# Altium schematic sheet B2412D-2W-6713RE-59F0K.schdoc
size 277 x 190 mm; Device: default297x210; Symbol: default297x210; Name: default297x210; Date: 2026.04.17; Rev: V1.0; Size: "A4"; Id: /; File: B2412D-2W-6713RE-59F0K; Sheet: /
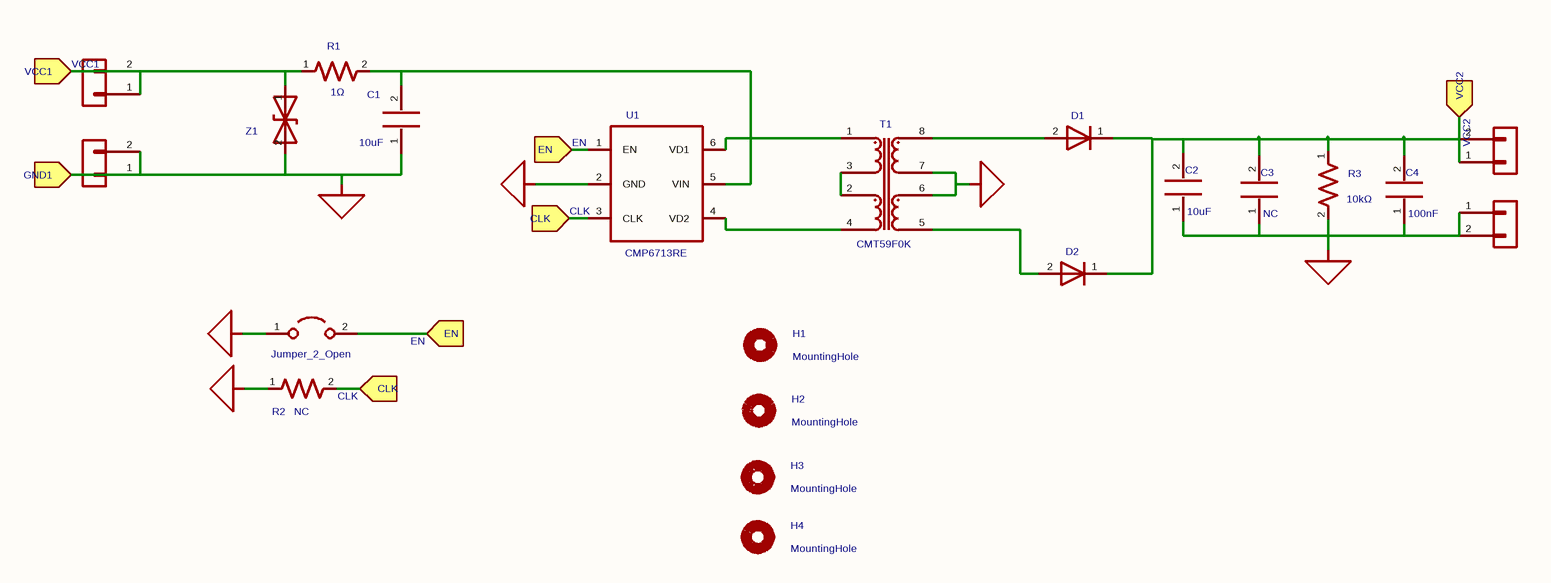
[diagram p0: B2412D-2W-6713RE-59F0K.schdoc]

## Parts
C1  10uF  [MYLibrary:C0805]
C2  10uF  [MYLibrary:C0805]
C3  value NC  [MYLibrary:C0805]  (hidden comment: My_Library_C)
C4  100nF  [MYLibrary:C0603]
D1  B5819WS  [MYLibrary:SOD-123-323]  (value not drawn)
D2  B5819WS  [MYLibrary:SOD-123-323]  (value not drawn)
H1  value MountingHole  [MountingHole:MountingHole_3.2mm_M3]  (hidden comment: Mechanical_MountingHole)
H2  value MountingHole  [MountingHole:MountingHole_3.2mm_M3]  (hidden comment: Mechanical_MountingHole)
H3  value MountingHole  [MountingHole:MountingHole_3.2mm_M3]  (hidden comment: Mechanical_MountingHole)
H4  value MountingHole  [MountingHole:MountingHole_3.2mm_M3]  (hidden comment: Mechanical_MountingHole)
J1  HX PZ2.54-1x2P ZZ  [Connector_PinHeader_2.54mm:PinHeader_1x02_P2.54mm_Vertical]  (value not drawn)
J2  HX PZ2.54-1x2P ZZ  [Connector_PinHeader_2.54mm:PinHeader_1x02_P2.54mm_Vertical]  (value not drawn)
J3  HX PZ2.54-1x2P ZZ  [Connector_PinHeader_2.54mm:PinHeader_1x02_P2.54mm_Vertical]  (value not drawn)
J4  HX PZ2.54-1x2P ZZ  [Connector_PinHeader_2.54mm:PinHeader_1x02_P2.54mm_Vertical]  (value not drawn)
JP1  value Jumper_2_Open  [Connector_PinHeader_2.54mm:PinHeader_1x02_P2.54mm_Vertical]  (hidden comment: HX PZ2.54-1x2P ZZ)
R1  1Ω  [MYLibrary:R0805]
R2  value NC  [MYLibrary:R0603]  (hidden comment: My_Library_R)
R3  10kΩ  [MYLibrary:R0603]
T1  CMT59F0K  [My Library:CMT59F0K]
U1  CMP6713RE  [My Library:CMP6713RE]
Z1  SMF28CA  [MYLibrary:SOD-123-323]  (value not drawn)

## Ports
CLK (in), EN (in), GND1 (in), VCC1 (in), VCC2 (in)

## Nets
GND1: C1.1 J4.1(Pin_1) J4.2(Pin_2) JP1.1(A) R2.1 U1.2(GND) Z1.2(A2) ; port GND1
GND2: C2.1 C3.1 C4.1 J3.1(Pin_1) J3.2(Pin_2) R3.2 T1.6 T1.7
CLK: R2.2 U1.3(CLK) ; port CLK
EN: JP1.2(B) U1.1(EN) ; port EN
VCC1: J1.1(Pin_1) J1.2(Pin_2) R1.1 Z1.1(A1) ; port VCC1
VCC2: C2.2 C3.2 C4.2 D1.1(K) D2.1(K) J2.1(Pin_1) J2.2(Pin_2) R3.1 ; port VCC2
NetC1_2: C1.2 R1.2 U1.5(VIN)
NetD1_2: D1.2(A) T1.8
NetD2_2: D2.2(A) T1.5
NetT1_1: T1.1 U1.6(VD1)
NetT1_2: T1.2 T1.3
NetT1_4: T1.4 U1.4(VD2)

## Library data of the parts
C1 = TCC0805X5R106K350FT: 容值:10uF;精度:±10%;额定电压:35V;温度系数:X5R;; Manufacturer: CCTC(三环); Symbol: My_Library_C; Add into BOM: yes; 3D Model: 1ba041120af144c991958decab20d241; 3D Model Transform: 78.74,51.181,0,0,0,0,0,0.0005,0; Tolerance: ±10%; Voltage Rating: 35V; Temperature Coefficient: X5R; ki_keywords: cap capacitor; ki_fp_filters: C_*; UniqueId: 5fb4f22ffcb6a001; ModelName: C0805_L2.0-W1.3-H1.3
C2 = 0805X106K250NT: 容值:10uF;精度:±10%;额定电压:25V;温度系数:X5R;; Manufacturer: FH(风华); Symbol: My_Library_C; Add into BOM: yes; 3D Model: 1ba041120af144c991958decab20d241; 3D Model Transform: 78.74,51.181,0,0,0,0,0,0.0005,0; Tolerance: ±10%; Voltage Rating: 25V; Temperature Coefficient: X5R; ki_keywords: cap capacitor; ki_fp_filters: C_*; UniqueId: 21d50210554cb61f; ModelName: C0805_L2.0-W1.3-H1.3
C3 = My_Library_C: Add into BOM: no; ki_keywords: cap capacitor; ki_fp_filters: C_*; UniqueId: ec64484c8c07847f; Attribute1: C1
C4 = CC0603KRX7R9BB104: 容值:100nF;精度:±10%;额定电压:50V;温度系数:X7R;; Manufacturer: YAGEO(国巨); Symbol: My_Library_C; Add into BOM: yes; 3D Model: ac125912035d415993ca9572d50418b1; 3D Model Transform: 62.992,31.496,0,0,0,0,0,0,0; Tolerance: ±10%; Voltage Rating: 50V; Temperature Coefficient: X7R; ki_keywords: cap capacitor; ki_fp_filters: C_*; UniqueId: 623e2bb2442f04df; ModelName: C0603_L1.6-W0.8-H0.8
D1 = B5819WS_C64886: 二极管配置:独立式;正向压降(Vf):900mV@3A;直流反向耐压(Vr):40V;整流电流:1A;; Manufacturer: MDD(辰达半导体); Symbol: My_Library_D; Add into BOM: yes; 3D Model: db63db13d9e342eb939127d413d6200b; 3D Model Transform: 104.3305,51.181,0,0,0,0,0,-0.004,0; Diode Configuration: 独立式; Voltage - DC Reverse(Vr): 40V; Current - Rectified: 1A; Reverse Leakage Current (Ir): 1mA@40V; Operating Junction Temperature Range: -55℃~+125℃; Non-Repetitive Peak Forward Surge Current: 25A; Value: D; ki_keywords: diode; ki_fp_filters: TO-???* *_Diode_* *SingleDiode* D_*; UniqueId: 07a0d5848cd81316; ModelName: SOD-323_L1.8-W1.3-LS2.5-RD
D2 = B5819WS_C64886: 二极管配置:独立式;正向压降(Vf):900mV@3A;直流反向耐压(Vr):40V;整流电流:1A;; Manufacturer: MDD(辰达半导体); Symbol: My_Library_D; Add into BOM: yes; 3D Model: db63db13d9e342eb939127d413d6200b; 3D Model Transform: 104.3305,51.181,0,0,0,0,0,-0.004,0; Diode Configuration: 独立式; Voltage - DC Reverse(Vr): 40V; Current - Rectified: 1A; Reverse Leakage Current (Ir): 1mA@40V; Operating Junction Temperature Range: -55℃~+125℃; Non-Repetitive Peak Forward Surge Current: 25A; Value: D; ki_keywords: diode; ki_fp_filters: TO-???* *_Diode_* *SingleDiode* D_*; UniqueId: fa5cd661465da5bc; ModelName: SOD-323_L1.8-W1.3-LS2.5-RD
H1-H4 = Mechanical_MountingHole: ki_fp_filters: MountingHole*; Attribute1: H1; AddInBom: yes
J1 = HX PZ2.54-1x2P ZZ: 插针结构:1x2P;间距:2.54mm;行距:-;圆针/方针:方针;安装方式:直插;排数:单排;总PIN位数:2P;额定电流:3A;额定电压:1kV;配合针长度:6mm;塑高:2.5mm;端接针长度:3mm;触头材质:黄铜;触头镀层:金;工作温度:-40℃~+105℃;颜色:黑色;; Manufacturer: hanxia(韩下); Symbol: Connector_Generic_Conn_01x02; Add into BOM: yes; 3D Model: c7a9f3c3e6e34627af2bf939e464cb35; 3D Model Transform: 200,100,0,0,0,0,0,0,-118.11; Pin Structure: 1x2P; Pitch: 2.54mm; Circluar Pins/Square Pins: 方针; Current Rating: 3A; Voltage Rating (Max): 1kV; ki_keywords: connector; ki_fp_filters: Connector*:*_1x??_*; UniqueId: 9f49826860c2c79d; ModelName: HDR-TH_2P-P2.54-M-LI-1X2P
J2 = HX PZ2.54-1x2P ZZ: 插针结构:1x2P;间距:2.54mm;行距:-;圆针/方针:方针;安装方式:直插;排数:单排;总PIN位数:2P;额定电流:3A;额定电压:1kV;配合针长度:6mm;塑高:2.5mm;端接针长度:3mm;触头材质:黄铜;触头镀层:金;工作温度:-40℃~+105℃;颜色:黑色;; Manufacturer: hanxia(韩下); Symbol: Connector_Generic_Conn_01x02; Add into BOM: yes; 3D Model: c7a9f3c3e6e34627af2bf939e464cb35; 3D Model Transform: 200,100,0,0,0,0,0,0,-118.11; Pin Structure: 1x2P; Pitch: 2.54mm; Circluar Pins/Square Pins: 方针; Current Rating: 3A; Voltage Rating (Max): 1kV; ki_keywords: connector; ki_fp_filters: Connector*:*_1x??_*; UniqueId: 42913bc3a3449998; ModelName: HDR-TH_2P-P2.54-M-LI-1X2P
J3 = HX PZ2.54-1x2P ZZ: 插针结构:1x2P;间距:2.54mm;行距:-;圆针/方针:方针;安装方式:直插;排数:单排;总PIN位数:2P;额定电流:3A;额定电压:1kV;配合针长度:6mm;塑高:2.5mm;端接针长度:3mm;触头材质:黄铜;触头镀层:金;工作温度:-40℃~+105℃;颜色:黑色;; Manufacturer: hanxia(韩下); Symbol: Connector_Generic_Conn_01x02; Add into BOM: yes; 3D Model: c7a9f3c3e6e34627af2bf939e464cb35; 3D Model Transform: 200,100,0,0,0,0,0,0,-118.11; Pin Structure: 1x2P; Pitch: 2.54mm; Circluar Pins/Square Pins: 方针; Current Rating: 3A; Voltage Rating (Max): 1kV; ki_keywords: connector; ki_fp_filters: Connector*:*_1x??_*; UniqueId: 6ca7fcf0d18ad80e; ModelName: HDR-TH_2P-P2.54-M-LI-1X2P
J4 = HX PZ2.54-1x2P ZZ: 插针结构:1x2P;间距:2.54mm;行距:-;圆针/方针:方针;安装方式:直插;排数:单排;总PIN位数:2P;额定电流:3A;额定电压:1kV;配合针长度:6mm;塑高:2.5mm;端接针长度:3mm;触头材质:黄铜;触头镀层:金;工作温度:-40℃~+105℃;颜色:黑色;; Manufacturer: hanxia(韩下); Symbol: Connector_Generic_Conn_01x02; Add into BOM: yes; 3D Model: c7a9f3c3e6e34627af2bf939e464cb35; 3D Model Transform: 200,100,0,0,0,0,0,0,-118.11; Pin Structure: 1x2P; Pitch: 2.54mm; Circluar Pins/Square Pins: 方针; Current Rating: 3A; Voltage Rating (Max): 1kV; ki_keywords: connector; ki_fp_filters: Connector*:*_1x??_*; UniqueId: 048fde32f53a6793; ModelName: HDR-TH_2P-P2.54-M-LI-1X2P
JP1 = HX PZ2.54-1x2P ZZ: 插针结构:1x2P;间距:2.54mm;行距:-;圆针/方针:方针;安装方式:直插;排数:单排;总PIN位数:2P;额定电流:3A;额定电压:1kV;配合针长度:6mm;塑高:2.5mm;端接针长度:3mm;触头材质:黄铜;触头镀层:金;工作温度:-40℃~+105℃;颜色:黑色;; Manufacturer: hanxia(韩下); Symbol: Jumper_Jumper_2_Open; Add into BOM: yes; 3D Model: c7a9f3c3e6e34627af2bf939e464cb35; 3D Model Transform: 200,100,0,0,0,0,0,0,-118.11; Pin Structure: 1x2P; Pitch: 2.54mm; Circluar Pins/Square Pins: 方针; Current Rating: 3A; Voltage Rating (Max): 1kV; ki_keywords: Jumper SPST; ki_fp_filters: Jumper* TestPoint*2Pads* TestPoint*Bridge*; UniqueId: ecd73cedbf8e787c; ModelName: HDR-TH_2P-P2.54-M-LI-1X2P
R1 = RC0805FR-071RL: 电阻类型:厚膜电阻;阻值:1Ω;精度:±1%;功率:125mW;工作电压:150V;温度系数:±200ppm/℃;; Manufacturer: YAGEO(国巨); Symbol: My_Library_R; Add into BOM: yes; 3D Model: 37a81e68749a4138bd2dfa6897b24b85; 3D Model Transform: 78.74,51.181,0,0,0,0,0,-0.0005,0; Tolerance: ±1%; Power(Watts): 125mW; Voltage-Supply(Max): 150V; ki_keywords: R res resistor; ki_fp_filters: R_*; UniqueId: 4e166b190d4de1c3; ModelName: R0805_L2.0-W1.3-H0.6
R2 = My_Library_R: Add into BOM: no; ki_keywords: R res resistor; ki_fp_filters: R_*; UniqueId: 7fed072ae61f3569; Attribute1: R3
R3 = RC0603FR-0710KL: 电阻类型:厚膜电阻;阻值:10kΩ;精度:±1%;功率:100mW;最大工作电压:75V;温度系数:±100ppm/℃;; Manufacturer: YAGEO(国巨); Symbol: My_Library_R; Add into BOM: yes; 3D Model: fc143cca1e79419f9cd78b61e9279f08; 3D Model Transform: 31.8897,63.7794,0,90,0,0,0,0,0; Tolerance: ±1%; Power(Watts): 100mW; Overload Voltage (Max): 75V; ki_keywords: R res resistor; ki_fp_filters: R_*; UniqueId: 6e26aea592918673; ModelName: R0603
T1 = Library_CMT59F0K: Origin Footprint: coileasy:XFMR-SMD; UniqueId: cf2c480e5945250c; Attribute1: T1; AddInBom: yes
U1 = MYLibrary_CMP6713RE: Origin Footprint: Package_TO_SOT_SMD:SOT-23-6; UniqueId: 48a4a086d8c42a18; Attribute1: U1; AddInBom: yes
Z1 = SMF28CA_C364280: 极性:双向;反向截止电压(Vrwm):28V;钳位电压:45.4V;峰值脉冲电流(Ipp):4.4A;峰值脉冲功率(Ppp):200W;击穿电压:34.4V;; Manufacturer: MDD(辰达半导体); Symbol: Diode_1N62xxCA; Add into BOM: yes; 3D Model: d105299b3871451c86f679efef28ff8f; 3D Model Transform: 145.669,70.866,0,0,0,0,0,0,0; Polarity: 双向; Reverse Stand-Off Voltage (Vrwm): 28V; Clamping Voltage: 45.4V; Peak Pulse Current (Ipp): 4.4A; Peak Pulse Power Dissipation (Ppp): 200W; Voltage - Breakdown: 34.4V; Reverse Leakage Current (Ir): 1uA; ki_keywords: diode TVS voltage suppressor; ki_fp_filters: D?DO?201AE*; Origin Footprint: Diode_THT:D_DO-201AE_P15.24mm_Horizontal; UniqueId: d022797895385730; ModelName: SOD-123FL_L2.8-W1.8-LS3.7-BI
